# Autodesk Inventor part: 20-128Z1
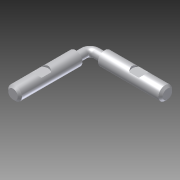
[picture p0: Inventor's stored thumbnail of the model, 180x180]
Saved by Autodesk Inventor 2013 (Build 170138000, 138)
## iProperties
Created: 2004-11
Part Number: 20-128Z1
Document SubType Name: Modeling
Designer: Autodesk, Inc.
Manufacturer: Standard
Standards Organization: Custom
Description: 90° MITRE CONNECTOR
Vendor: PARKER IPS
Mass: 2.13496 g
Surface Area: 14.8989 cm^2
Volume: 2.13496 cm^3
Density: 1 g/cm^3
Sheet Metal Rule: Default
Material: Allgemein
CAGE: 1LJX3
Dept. ID: Product Design
Description #2: ---
Finish #1: ---
Finish #2: ---
Material ID: ---
Project Number: ---
Author: Autodesk, Inc.
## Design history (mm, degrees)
workplane "Work Plane1"
sketch "Sketch1"
  geometry: C1 r 3.285 at (0, 0)
  constraints: 1 centre point, 1 other
  dimensions: "d0" = 6.57 diameter of C1
extrude "Extrusion1" new body sketch "Sketch1" distance "d1" = 30; taper "d2" = 0 deg
chamfer "Chamfer1" distance "d7" = 1; stored, may be unused: second distance "d8" = 2, angle "d9" = 45 deg
workplane "Work Plane2"
sketch "Sketch2"
  geometry: L1 (3.285, 0)-(3.285, 29) reference; L2 (-3.285, 0)-(-3.285, 29) reference; C1 r 3.285 at (0, 16.4); 1 further point
  constraints: 2 tangent, 1 centre point
  dimensions: "d10" = 23.4 distance of point (0, -7) C1.centre
extrude "Extrusion2" cut sketch "Sketch2" distance "d11" = 1; taper "d12" = 0 deg
pattern_circular "Circular Pattern1" dims "d6" = 90 deg
sweep "Sweep1" dims "d15" = 0
body "Solid1"
sketch "Sketch3"
  geometry: L1 (-7, -3.285)-(-7, 3.285) reference; L2 (-3.285, 7)-(3.285, 7) reference; L3 (-7, 0)-(-3, 0); L4 (0, 3)-(0, 7); A1 r 3 centre (-3, 3) between (-3, 0) and (0, 3)
  constraints: 4 end point, 2 midpoint, 2 point on circle, 2 tangent, 1 centre point, 1 parallel, 1 vertical
  dimensions: "d13" = 3 radius of A1
sketch "Sketch4"
  geometry: C1 r 3.285 at (0, 0) reference; C2 r 2 at (0, 0)
  constraints: 1 centre point, 1 coincident
  dimensions: "d14" = 4 diameter of C2
other parameters: "Thickness" = 3.048, "BendRadius" = 3.048 (= Thickness), "BendReliefWidth" = 3.048 (= Thickness), "BendReliefDepth" = 1.524 (= 0.5 x Thickness), "CornerReliefSize" = 12.192 (= 4 x Thickness), "SeamGap" = 0.00508, "MinimumRemnant" = 6.096 (= 2 x Thickness), "TransitionRadius" = 3.048 (= BendRadius), "d3" = 7, "JacobiRadiusSize" = 3.048 (= Thickness), "GapSize" = 3.048 (= Thickness)
